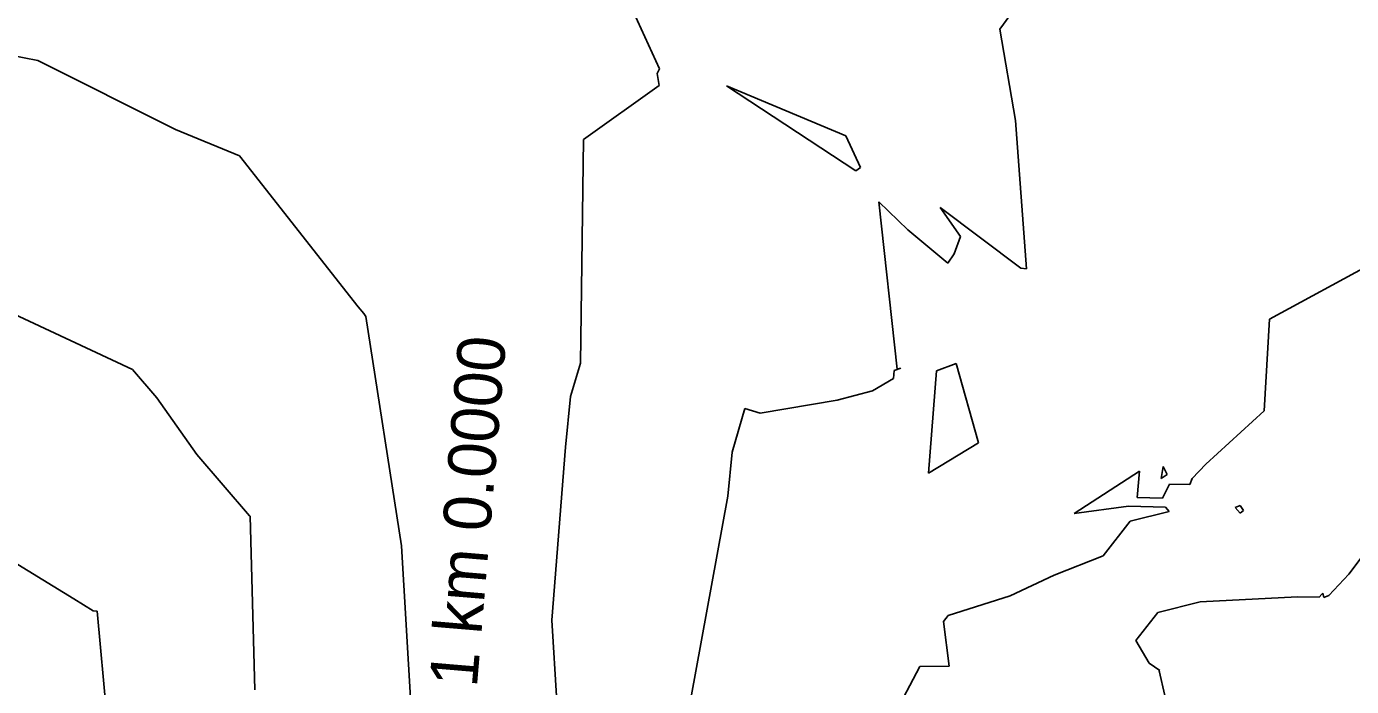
# Model space of a CAD drawing. Extents: x -549394 to -546608, y -1037055 to -1033629.
# Drawn here: x -547750.8 to -547499.1, y -1035100.8 to -1034975.5 of the extents above; entities that cross this region are included whole.
import ezdxf

# ---------------------------------------------------------------- set-up
doc = ezdxf.new("R2010")
doc.units = 0
for name, color, linetype in [('hlavni_vrst', 7, 'Continuous'), ('norm_vrst', 7, 'Continuous'), ('x_popis_pricne_rezy_C21', 7, 'Continuous')]:
    doc.layers.add(name, color=color, linetype=linetype)

msp = doc.modelspace()

# ---------------------------------------------------------------- linework, layer by layer
at = {"layer": 'hlavni_vrst'}
for p, q in [((-547630.53, -1034983.54), (-547640.27, -1034962.33)), ((-547630.97, -1034984.44), (-547630.53, -1034983.54)), ((-547630.58, -1034986.73), (-547630.97, -1034984.44)), ((-547644.96, -1034996.95), (-547630.58, -1034986.73)), ((-547645.56, -1035039.41), (-547644.96, -1034996.95)), ((-547647.45, -1035045.8), (-547645.56, -1035039.41)), ((-547648.39, -1035055.39), (-547647.45, -1035045.8)), ((-547650.97, -1035088.23), (-547648.39, -1035055.39)), ((-547650.05, -1035103.66), (-547650.97, -1035088.23))]:
    msp.add_line(p, q, dxfattribs=at)
at = {"layer": 'norm_vrst'}
for p, q in [((-547565.89, -1034976.01), (-547553.79, -1034959.56)), ((-547562.89, -1034993.39), (-547565.89, -1034976.01)), ((-547748.61, -1034981.97), (-547757.67, -1034980.24)), ((-547722.51, -1034995.06), (-547748.61, -1034981.97)), ((-547593.26, -1035002.94), (-547617.79, -1034986.8)), ((-547617.79, -1034986.8), (-547595.13, -1034996.25)), ((-547710.32, -1035000.08), (-547722.51, -1034995.06)), ((-547560.84, -1035021.55), (-547562.89, -1034993.39)), ((-547595.13, -1034996.25), (-547592.37, -1035002.28)), ((-547687.81, -1035028.74), (-547710.32, -1035000.08)), ((-547592.37, -1035002.28), (-547593.26, -1035002.94)), ((-547588.88, -1035008.82), (-547583.39, -1035014.14)), ((-547585.36, -1035040.55), (-547588.88, -1035008.82)), ((-547573.36, -1035015.36), (-547577.22, -1035009.9)), ((-547577.22, -1035009.9), (-547561.9, -1035021.39)), ((-547583.39, -1035014.14), (-547575.79, -1035020.48)), ((-547574.57, -1035018.71), (-547573.36, -1035015.36)), ((-547575.79, -1035020.48), (-547574.57, -1035018.71)), ((-547514.67, -1035031.07), (-547494.58, -1035020.17)), ((-547561.9, -1035021.39), (-547560.84, -1035021.55)), ((-547730.63, -1035040.65), (-547754.19, -1035029.66)), ((-547686.72, -1035030.03), (-547687.81, -1035028.74)), ((-547686.33, -1035030.57), (-547686.72, -1035030.03)), ((-547679.55, -1035074.12), (-547686.33, -1035030.57)), ((-547515.69, -1035048.49), (-547514.67, -1035031.07)), ((-547726.04, -1035046.05), (-547730.63, -1035040.65)), ((-547586.09, -1035042.33), (-547585.98, -1035040.86)), ((-547585.98, -1035040.86), (-547584.68, -1035040.37)), ((-547584.68, -1035040.37), (-547585.36, -1035040.55)), ((-547579.44, -1035060.31), (-547577.91, -1035040.91)), ((-547577.91, -1035040.91), (-547574.2, -1035039.51)), ((-547574.2, -1035039.51), (-547569.97, -1035054.57)), ((-547590.08, -1035044.68), (-547586.09, -1035042.33)), ((-547718.45, -1035056.77), (-547726.04, -1035046.05)), ((-547596.78, -1035046.48), (-547590.08, -1035044.68)), ((-547616.75, -1035056.34), (-547614.3, -1035048.04)), ((-547614.3, -1035048.04), (-547611.44, -1035048.93)), ((-547611.44, -1035048.93), (-547596.78, -1035046.48)), ((-547526.74, -1035058.63), (-547515.69, -1035048.49)), ((-547741.82, -1035084.17), (-547799.24, -1035049.25)), ((-547569.97, -1035054.57), (-547579.44, -1035060.31)), ((-547499.6, -1035079.52), (-547480.94, -1035054.58)), ((-547708.45, -1035068.43), (-547718.45, -1035056.77)), ((-547617.56, -1035064.71), (-547616.75, -1035056.34)), ((-547529.36, -1035061.34), (-547526.74, -1035058.63)), ((-547551.78, -1035067.99), (-547539.33, -1035059.97)), ((-547539.33, -1035059.97), (-547539.8, -1035064.93)), ((-547535.26, -1035061.32), (-547534.84, -1035059.05)), ((-547534.1, -1035060.59), (-547535.26, -1035061.32)), ((-547534.84, -1035059.05), (-547534.1, -1035060.59)), ((-547535.01, -1035065.1), (-547533.68, -1035062.42)), ((-547533.68, -1035062.42), (-547529.79, -1035062.46)), ((-547529.79, -1035062.46), (-547529.36, -1035061.34)), ((-547624.56, -1035103.1), (-547617.56, -1035064.71)), ((-547539.8, -1035064.93), (-547535.01, -1035065.1)), ((-547708.32, -1035068.47), (-547708.45, -1035068.43)), ((-547707.41, -1035101.49), (-547708.32, -1035068.47)), ((-547541.44, -1035066.59), (-547551.78, -1035067.99)), ((-547534.39, -1035066.81), (-547541.44, -1035066.59)), ((-547541.11, -1035069.46), (-547533.73, -1035067.58)), ((-547533.73, -1035067.58), (-547534.39, -1035066.81)), ((-547520.21, -1035066.44), (-547521.2, -1035066.83)), ((-547521.2, -1035066.83), (-547520.26, -1035067.93)), ((-547520.26, -1035067.93), (-547519.62, -1035067.42)), ((-547519.62, -1035067.42), (-547520.21, -1035066.44)), ((-547546.28, -1035076.04), (-547541.11, -1035069.46)), ((-547677.77, -1035104.15), (-547679.55, -1035074.12)), ((-547555.56, -1035079.72), (-547546.28, -1035076.04)), ((-547563.91, -1035083.64), (-547555.56, -1035079.72)), ((-547503.4, -1035083.58), (-547499.6, -1035079.52)), ((-547575.71, -1035087.34), (-547563.91, -1035083.64)), ((-547505.24, -1035083.85), (-547504.71, -1035083.33)), ((-547504.71, -1035083.33), (-547504.53, -1035083.09)), ((-547504.53, -1035083.09), (-547504.35, -1035083.91)), ((-547504.35, -1035083.91), (-547503.4, -1035083.58)), ((-547738.15, -1035086.44), (-547741.82, -1035084.17)), ((-547535.88, -1035086.78), (-547527.84, -1035084.74)), ((-547527.84, -1035084.74), (-547509.37, -1035083.84)), ((-547509.37, -1035083.84), (-547505.24, -1035083.85)), ((-547737.39, -1035086.56), (-547738.15, -1035086.44)), ((-547729.82, -1035167.54), (-547737.39, -1035086.56)), ((-547737.39, -1035086.56), (-547737.39, -1035086.56)), ((-547737.39, -1035086.56), (-547737.39, -1035086.56)), ((-547737.39, -1035086.56), (-547737.39, -1035086.56)), ((-547576.61, -1035088.51), (-547575.71, -1035087.34)), ((-547575.48, -1035097), (-547576.61, -1035088.51)), ((-547540.04, -1035092.08), (-547535.88, -1035086.78)), ((-547537.54, -1035096.4), (-547540.04, -1035092.08)), ((-547593.1, -1035119.88), (-547581.07, -1035097.02)), ((-547581.07, -1035097.02), (-547575.48, -1035097)), ((-547535.49, -1035097.8), (-547537.54, -1035096.4)), ((-547535.61, -1035097.89), (-547535.49, -1035097.8)), ((-547534.57, -1035102.57), (-547535.61, -1035097.89))]:
    msp.add_line(p, q, dxfattribs=at)

# ---------------------------------------------------------------- texts
at = {"layer": 'x_popis_pricne_rezy_C21'}
msp.add_text('PŘ 1 km 0.0000', height=9.0627, rotation=85.1934, dxfattribs=at).set_placement((-547666.93, -1035121.29))

doc.saveas('drawing.dxf')
